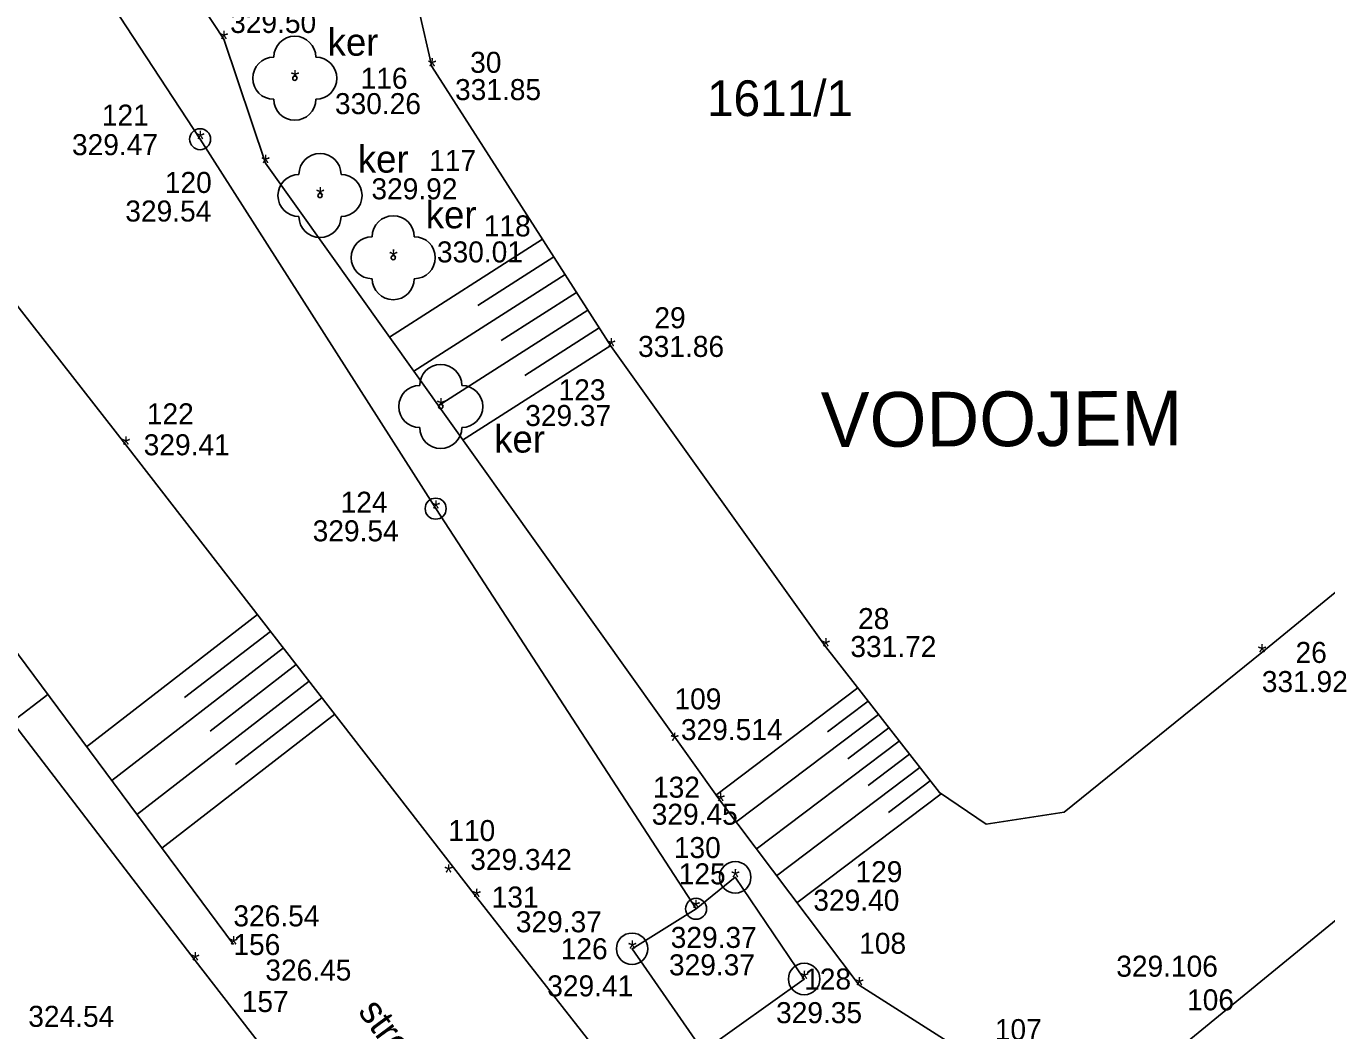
# Model space of a CAD drawing. Extents: x -600587 to -600377, y -1159886 to -1159708.
# Drawn here: x -600513.58 to -600482.67, y -1159827.23 to -1159803.35 of the extents above; entities that cross this region are included whole.
import ezdxf

# ---------------------------------------------------------------- set-up
doc = ezdxf.new("R2010")
doc.units = 0
for name, color, linetype in [('Parcelní čísla', 7, 'Continuous'), ('Vrstva 11', 7, 'Continuous'), ('Vrstva 12', 7, 'Continuous'), ('Vrstva 13', 7, 'Continuous'), ('Vrstva 22', 7, 'Continuous'), ('Vrstva 40', 7, 'Continuous'), ('Vrstva 58', 7, 'Continuous'), ('Vrstva 59', 7, 'Continuous'), ('Vrstva 60', 7, 'Continuous'), ('Vrstva 8', 7, 'Continuous')]:
    doc.layers.add(name, color=color, linetype=linetype)

msp = doc.modelspace()

# ---------------------------------------------------------------- linework, layer by layer
at = {"layer": 'Vrstva 11'}
for p, q in [((-600501.3, -1159808.42), (-600504.94, -1159810.75)), ((-600501.03, -1159808.84), (-600502.84, -1159810)), ((-600500.76, -1159809.26), (-600504.36, -1159811.56)), ((-600500.49, -1159809.69), (-600502.28, -1159810.83)), ((-600500.22, -1159810.11), (-600503.78, -1159812.38)), ((-600499.95, -1159810.53), (-600501.72, -1159811.66)), ((-600499.68, -1159810.95), (-600503.2, -1159813.2)), ((-600508.08, -1159817.35), (-600512.14, -1159820.5)), ((-600507.77, -1159817.75), (-600509.81, -1159819.32)), ((-600507.46, -1159818.14), (-600511.54, -1159821.3)), ((-600507.16, -1159818.54), (-600509.2, -1159820.12)), ((-600506.85, -1159818.93), (-600510.95, -1159822.11)), ((-600513.91, -1159819.9), (-600513.06, -1159819.25)), ((-600506.55, -1159819.33), (-600508.6, -1159820.92)), ((-600493.802, -1159819.095), (-600497.185, -1159821.651)), ((-600493.556, -1159819.411), (-600494.525, -1159820.142)), ((-600506.24, -1159819.72), (-600510.35, -1159822.91)), ((-600493.31, -1159819.727), (-600496.703, -1159822.289)), ((-600493.065, -1159820.042), (-600494.043, -1159820.781)), ((-600492.819, -1159820.358), (-600496.221, -1159822.927)), ((-600492.573, -1159820.673), (-600493.56, -1159821.419)), ((-600492.327, -1159820.989), (-600495.739, -1159823.566)), ((-600492.081, -1159821.304), (-600493.078, -1159822.058)), ((-600491.823, -1159821.611), (-600495.257, -1159824.204))]:
    msp.add_line(p, q, dxfattribs=at)
for points in [[(-600516.94, -1159753.09), (-600529.19, -1159763.15), (-600531.78, -1159762.08), (-600536.7, -1159765.98), (-600536.54, -1159767.38), (-600523.4, -1159784.58), (-600513.95, -1159795.95), (-600508.88, -1159803.66), (-600507.89, -1159806.61), (-600497.07, -1159821.79)], [(-600484.2, -1159818.25), (-600488.9, -1159822.049), (-600490.752, -1159822.336), (-600491.864, -1159821.583), (-600494.57, -1159818.11), (-600499.67, -1159810.97), (-600503.93, -1159804.31), (-600504.24, -1159802.96), (-600504.53, -1159801.26), (-600507.92, -1159797.32), (-600520.37, -1159782.44), (-600531.29, -1159768.93), (-600531.09, -1159768.27), (-600517.61, -1159757.68), (-600517.26, -1159757.72), (-600510.67, -1159766.03), (-600510.22, -1159766.67), (-600508.71, -1159768.78)], [(-600502.72, -1159834.41), (-600509.56, -1159825.58), (-600519.31, -1159812.85), (-600530.48, -1159797.91), (-600554.16, -1159766.46)], [(-600541.29, -1159772.5), (-600530.96, -1159787.09), (-600518.71, -1159803.7), (-600511.21, -1159813.31), (-600502.87, -1159824.07)], [(-600508.65, -1159825.2), (-600518.33, -1159812.15), (-600529.24, -1159796.96), (-600545.67, -1159772.91)], [(-600476.58, -1159802.04), (-600473.23, -1159806.46), (-600472.64, -1159808.01), (-600473.31, -1159809.34), (-600484.2, -1159818.25)], [(-600472.677, -1159816.619), (-600485.977, -1159827.515), (-600490.548, -1159828.224), (-600493.772, -1159826.17), (-600497.07, -1159821.79)], [(-600502.87, -1159824.07), (-600498.564, -1159829.569), (-600492.522, -1159832.403), (-600487.072, -1159831.78), (-600481.048, -1159829.438), (-600476.419, -1159825.97)]]:
    msp.add_lwpolyline(points, dxfattribs=at)
for centre, radius in [((-600496.72, -1159823.6), 0.375), ((-600496.72, -1159823.6), 0.0005), ((-600499.17, -1159825.301), 0.375), ((-600499.17, -1159825.301), 0.0005), ((-600495.08, -1159826.021), 0.375), ((-600495.08, -1159826.021), 0.0005)]:
    msp.add_circle(centre, radius, dxfattribs=at)
at = {"layer": 'Vrstva 12'}
msp.add_lwpolyline([(-600499.17, -1159825.3), (-600497.48, -1159827.74), (-600495.08, -1159826.02), (-600496.72, -1159823.6), (-600497.65, -1159824.35)], close=True, dxfattribs=at)
at = {"layer": 'Vrstva 13'}
msp.add_lwpolyline([(-600497.65, -1159824.35), (-600503.84, -1159814.83), (-600509.44, -1159806.04), (-600515.67, -1159796.54), (-600524.06, -1159785.44), (-600517.8, -1159780.23), (-600516.59, -1159779.24)], dxfattribs=at)
at = {"layer": 'Vrstva 22'}
for centre in [(-600507.19, -1159804.59), (-600506.59, -1159807.38), (-600504.85, -1159808.86), (-600503.72, -1159812.4)]:
    msp.add_circle(centre, 0.05, dxfattribs=at)
for centre, start, end in [((-600507.19, -1159804.09), 0, 180), ((-600507.69, -1159804.59), 90, 270), ((-600506.69, -1159804.59), 270, 90), ((-600507.19, -1159805.09), 180, 0), ((-600506.59, -1159806.88), 0, 180), ((-600507.09, -1159807.38), 90, 270), ((-600506.09, -1159807.38), 270, 90), ((-600506.59, -1159807.88), 180, 0), ((-600504.85, -1159808.36), 0, 180), ((-600505.35, -1159808.86), 90, 270), ((-600504.35, -1159808.86), 270, 90), ((-600504.85, -1159809.36), 180, 0), ((-600503.72, -1159811.9), 0, 180), ((-600504.22, -1159812.4), 90, 270), ((-600503.22, -1159812.4), 270, 90), ((-600503.72, -1159812.9), 180, 0)]:
    msp.add_arc(centre, 0.5, start, end, dxfattribs=at)
at = {"layer": 'Vrstva 8'}
for centre, radius in [((-600509.441, -1159806.04), 0.25), ((-600509.441, -1159806.04), 0.0005), ((-600503.841, -1159814.83), 0.25), ((-600503.841, -1159814.83), 0.0005), ((-600497.65, -1159824.35), 0.25), ((-600497.65, -1159824.35), 0.0005)]:
    msp.add_circle(centre, radius, dxfattribs=at)

# ---------------------------------------------------------------- texts
at = {"layer": 'Parcelní čísla'}
msp.add_text('1611/1', height=0.85, dxfattribs=at).set_placement((-600497.392, -1159805.49))
at = {"layer": 'Vrstva 40'}
for p in [(-600506.409, -1159804.054), (-600505.691, -1159806.836), (-600504.077, -1159808.16), (-600502.449, -1159813.496)]:
    msp.add_text('ker', height=0.65, dxfattribs=at).set_placement(p)
for s, height, rotation, p in [('VODOJEM', 1.3, 0.2526, (-600494.682, -1159813.363)), ('stromy a kere', 0.65, 306.4091, (-600505.705, -1159826.794))]:
    msp.add_text(s, height=height, rotation=rotation, dxfattribs=at).set_placement(p)
at = {"layer": 'Vrstva 58'}
for s, p in [('329.50', (-600508.727, -1159803.513)), ('331.85', (-600503.38, -1159805.11)), ('330.26', (-600506.235, -1159805.444)), ('329.47', (-600512.487, -1159806.42)), ('329.92', (-600505.368, -1159807.47)), ('329.54', (-600511.219, -1159807.999)), ('330.01', (-600503.811, -1159808.972)), ('331.86', (-600499.029, -1159811.22)), ('329.37', (-600501.712, -1159812.864)), ('329.41', (-600510.782, -1159813.56)), ('329.54', (-600506.765, -1159815.607)), ('331.72', (-600493.982, -1159818.36)), ('331.92', (-600484.2, -1159819.193)), ('329.514', (-600498.01, -1159820.337)), ('329.45', (-600498.704, -1159822.35)), ('329.342', (-600503.019, -1159823.427)), ('329.40', (-600494.862, -1159824.395)), ('326.54', (-600508.65, -1159824.768)), ('329.37', (-600501.935, -1159824.908)), ('329.37', (-600498.253, -1159825.28)), ('329.37', (-600498.294, -1159825.933)), ('329.106', (-600487.66, -1159825.965)), ('326.45', (-600507.89, -1159826.057)), ('329.41', (-600501.188, -1159826.433)), ('324.54', (-600513.526, -1159827.158)), ('329.35', (-600495.748, -1159827.07))]:
    msp.add_text(s, height=0.5, dxfattribs=at).set_placement(p)
at = {"layer": 'Vrstva 59'}
for s, p in [('30', (-600503.021, -1159804.461)), ('116', (-600505.625, -1159804.84)), ('121', (-600511.777, -1159805.717)), ('117', (-600503.994, -1159806.797)), ('120', (-600510.28, -1159807.319)), ('118', (-600502.697, -1159808.353)), ('29', (-600498.641, -1159810.538)), ('123', (-600500.918, -1159812.253)), ('122', (-600510.708, -1159812.824)), ('124', (-600506.1, -1159814.927)), ('28', (-600493.799, -1159817.695)), ('26', (-600483.398, -1159818.5)), ('109', (-600498.163, -1159819.606)), ('132', (-600498.674, -1159821.707)), ('110', (-600503.54, -1159822.738)), ('130', (-600498.179, -1159823.143)), ('125', (-600498.062, -1159823.767)), ('129', (-600493.86, -1159823.716)), ('131', (-600502.509, -1159824.32)), ('156', (-600508.65, -1159825.45)), ('126', (-600500.867, -1159825.55)), ('108', (-600493.772, -1159825.42)), ('128', (-600495.08, -1159826.27)), ('157', (-600508.451, -1159826.806)), ('106', (-600485.977, -1159826.765)), ('107', (-600490.548, -1159827.474))]:
    msp.add_text(s, height=0.5, dxfattribs=at).set_placement(p)
at = {"layer": 'Vrstva 60'}
for p in [(-600508.978, -1159803.86), (-600504.028, -1159804.51), (-600507.288, -1159804.79), (-600509.538, -1159806.24), (-600507.988, -1159806.81), (-600506.688, -1159807.58), (-600504.948, -1159809.06), (-600499.768, -1159811.17), (-600503.818, -1159812.6), (-600511.308, -1159813.51), (-600503.938, -1159815.03), (-600494.668, -1159818.31), (-600484.298, -1159818.45), (-600498.261, -1159820.556), (-600497.168, -1159821.99), (-600503.638, -1159823.688), (-600496.818, -1159823.8), (-600502.968, -1159824.27), (-600497.758, -1159824.53), (-600508.748, -1159825.4), (-600499.268, -1159825.5), (-600509.658, -1159825.78), (-600495.178, -1159826.22), (-600493.87, -1159826.37)]:
    msp.add_text('*', height=0.4, dxfattribs=at).set_placement(p)

doc.saveas('drawing.dxf')
